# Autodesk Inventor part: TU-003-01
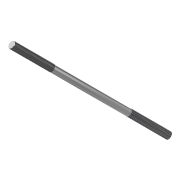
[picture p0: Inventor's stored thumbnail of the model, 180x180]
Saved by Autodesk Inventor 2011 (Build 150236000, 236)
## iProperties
Created: 2002-07
Part Number: TU-003-01
Material: Stainless Steel
Description: Rod - 35 mm stroke length
Document SubType Name: Modeling
Designer: PN
Mass: 18.7131 g
Surface Area: 18.8805 cm^2
Volume: 2.31598 cm^3
Density: 8.08 g/cm^3
Author: PN
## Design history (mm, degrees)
derived "M5 Threaded Rod.ipt" dims "d0" = 5, "d1" = 118, "d2" = 0, "d3" = 0.25, "d6" = 0, "d9" = 0
body "Solid1"
feature "Solid1::M5 Threaded Rod.ipt" dims "d0" = 5, "d1" = 118, "d2" = 0, "d3" = 0.25, "d5" = 30, "d6" = 0, "d8" = 30, "d9" = 0, "ScaleForDerivedMember" = 10
tag "TaggingFeature1"
